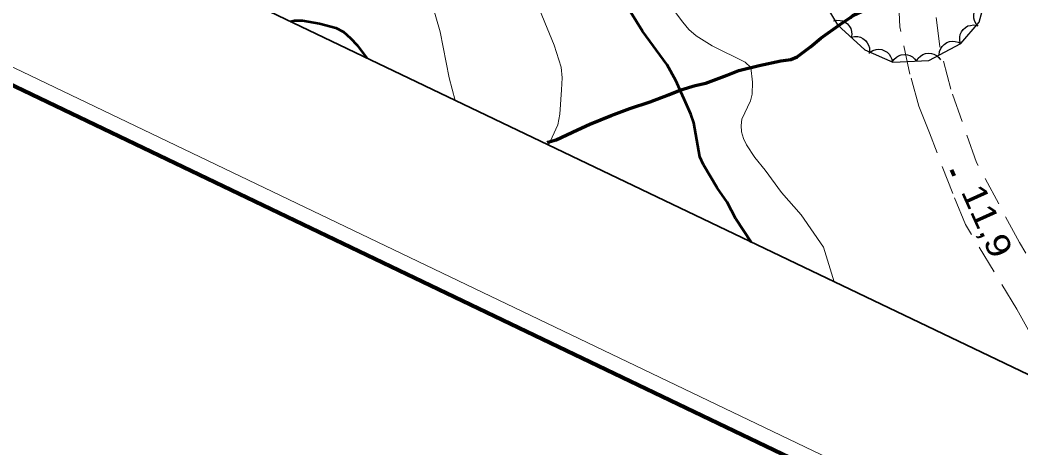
# Model space of a CAD drawing. Extents: x 355726 to 357533, y 5103782 to 5105258.
# Drawn here: x 355806.3 to 355868.2, y 5104403.8 to 5104430.3 of the extents above; entities that cross this region are included whole.
import ezdxf

# ---------------------------------------------------------------- set-up
doc = ezdxf.new("R2010")
doc.units = 0
doc.header["$LTSCALE"] = 0.6
for name, pattern in [('DOT_DASHED', [7.7, 5, -1.2, 0.3, -1.2]), ('LONG_DASHED', [7.5, 6, -1.5]), ('MEDIUM_DASHED', [4.5, 3, -1.5])]:
    doc.linetypes.add(name, pattern=pattern)
for name, color, linetype, lineweight in [('1', 7, 'LONG_DASHED', 53), ('19', 7, 'Continuous', 13), ('2', 7, 'LONG_DASHED', 13), ('22', 7, 'Continuous', 13), ('3', 7, 'Continuous', 140), ('44', 7, 'Continuous', 25), ('60', 7, 'Continuous', 13)]:
    doc.layers.add(name, color=color, linetype=linetype, lineweight=lineweight)

msp = doc.modelspace()

# ---------------------------------------------------------------- linework, layer by layer
at = {"layer": '1', "linetype": 'Continuous'}
msp.add_lwpolyline([(355851.59, 5104416.57), (355850.64, 5104418.01), (355850.1, 5104419.05), (355849.48, 5104419.93), (355848.64, 5104421.36), (355848.42, 5104421.84), (355848.04, 5104423.96), (355847.85, 5104424.48), (355846.92, 5104426.57), (355846.38, 5104427.55), (355844.86, 5104429.63), (355843.85, 5104431.26)], dxfattribs=at)
at = {"layer": '1'}
msp.add_lwpolyline([(355823.06, 5104430.23), (355823.3, 5104430.29), (355823.8, 5104430.3), (355824.85, 5104430.11), (355825.86, 5104429.84), (355826.34, 5104429.59), (355826.78, 5104429.2), (355827.19, 5104428.76), (355827.79, 5104427.96)], dxfattribs=at)
at = {"layer": '19', "linetype": 'MEDIUM_DASHED'}
for points in [[(355870.09, 5104408.75), (355868.05, 5104412.41), (355864.88, 5104417.65), (355864.08, 5104419.57), (355862.64, 5104423.33), (355861.99, 5104424.98), (355861.43, 5104426.97), (355860.8, 5104429.89), (355860.71, 5104431.93), (355860.63, 5104433.62), (355860.67, 5104435.27), (355860.96, 5104438.95), (355862.04, 5104446.11), (355862.5, 5104448.51), (355863.18, 5104450.59), (355863.73, 5104453.33), (355864.37, 5104455.53), (355864.99, 5104458.03), (355865.95, 5104460.45), (355867.14, 5104463.61), (355867.98, 5104465.8), (355869.15, 5104468.59)], [(355871.35, 5104411.24), (355868.21, 5104416.55), (355865.56, 5104421.49), (355863.97, 5104426.03), (355863.28, 5104428.68), (355862.92, 5104431.54), (355862.93, 5104434.2), (355863.07, 5104436.38), (355863.26, 5104438.83), (355863.47, 5104440.78), (355864, 5104442.94), (355865.27, 5104449.22), (355865.5, 5104450.86), (355865.8, 5104452.26), (355866.17, 5104453.63), (355866.58, 5104454.88), (355867.83, 5104459.2), (355868.43, 5104460.43)]]:
    msp.add_lwpolyline(points, dxfattribs=at)
at = {"layer": '2'}
for points in [[(355831.75, 5104431.61), (355832.32, 5104429.59), (355832.88, 5104426.74), (355833.25, 5104425.34)], [(355839.04, 5104422.58), (355839.62, 5104423.82), (355839.75, 5104424.5), (355839.85, 5104425.99), (355839.88, 5104426.73), (355839.82, 5104427.41), (355839.39, 5104428.76), (355838.19, 5104431.7)]]:
    msp.add_lwpolyline(points, dxfattribs=at)
at = {"layer": '2', "linetype": 'Continuous'}
msp.add_lwpolyline([(355856.74, 5104414.11), (355856.07, 5104416.25), (355854.69, 5104418.26), (355853.47, 5104419.63), (355852.46, 5104421.03), (355851.82, 5104421.8), (355851.3, 5104422.59), (355851.11, 5104422.99), (355850.99, 5104423.4), (355850.97, 5104423.79), (355851.02, 5104424.18), (355851.56, 5104425.32), (355851.65, 5104425.72), (355851.68, 5104426.48), (355851.58, 5104427.38), (355851.22, 5104427.7), (355849.17, 5104428.73), (355848.18, 5104429.34), (355847.74, 5104429.74), (355847.36, 5104430.18), (355846.6, 5104431.2)], dxfattribs=at)
at = {"layer": '22', "linetype": 'LONG_DASHED', "lineweight": 70}
msp.add_lwpolyline([(355838.96, 5104422.73), (355839, 5104422.75), (355839.51, 5104422.91), (355840.83, 5104423.51), (355841.6, 5104423.88), (355842.93, 5104424.41), (355844.07, 5104424.84), (355845.34, 5104425.26), (355846.48, 5104425.68), (355847.24, 5104425.99), (355848.13, 5104426.26), (355848.78, 5104426.41), (355850.11, 5104426.9), (355850.82, 5104427.2), (355852.09, 5104427.51), (355853.44, 5104427.79), (355854.06, 5104427.88), (355854.45, 5104428.04), (355855.26, 5104428.66), (355855.91, 5104429.2), (355857.13, 5104430.07), (355857.75, 5104430.48), (355857.89, 5104430.59), (355860.71, 5104431.93)], dxfattribs=at)
at = {"layer": '3'}
msp.add_line((355864.01, 5104421.04), (355864.17, 5104420.67), dxfattribs=at)
at = {"layer": '44', "linetype": 'DOT_DASHED'}
msp.add_lwpolyline([(355869.03, 5104478.9), (355864.17, 5104473.77), (355861.32, 5104470.45), (355858.63, 5104465.67), (355856.61, 5104460.32), (355854.91, 5104455.18), (355853.82, 5104450.09), (355853.27, 5104446.66), (355853.06, 5104443.83), (355852.88, 5104440), (355853, 5104437.76), (355853.94, 5104434.87), (355856.95, 5104430.03), (355858.64, 5104428.48), (355860.37, 5104427.7), (355862.61, 5104427.82), (355864.58, 5104428.87), (355865.72, 5104430.19), (355866.1, 5104431.56), (355866.58, 5104435.22), (355867.9, 5104437.23), (355870.74, 5104440.15)], dxfattribs=at)
at = {"layer": '44'}
for points in [[(355865.65, 5104429.94), (355865.52, 5104430.1), (355865.43, 5104430.29), (355865.39, 5104430.44), (355865.39, 5104430.62), (355865.42, 5104430.8), (355865.51, 5104430.98), (355865.59, 5104431.12), (355865.72, 5104431.23), (355865.88, 5104431.33), (355866.05, 5104431.39)], [(355856.69, 5104430.27), (355856.9, 5104430.31), (355857.1, 5104430.3), (355857.26, 5104430.27), (355857.42, 5104430.19), (355857.56, 5104430.08), (355857.68, 5104429.92), (355857.77, 5104429.79), (355857.81, 5104429.61), (355857.83, 5104429.43), (355857.8, 5104429.25)], [(355864.57, 5104428.86), (355864.52, 5104429.06), (355864.52, 5104429.26), (355864.55, 5104429.43), (355864.63, 5104429.58), (355864.73, 5104429.73), (355864.88, 5104429.86), (355865.02, 5104429.95), (355865.19, 5104429.99), (355865.37, 5104430.02), (355865.55, 5104429.99)], [(355857.8, 5104429.25), (355858, 5104429.3), (355858.2, 5104429.29), (355858.37, 5104429.26), (355858.52, 5104429.17), (355858.67, 5104429.06), (355858.79, 5104428.91), (355858.87, 5104428.77), (355858.92, 5104428.6), (355858.93, 5104428.42), (355858.9, 5104428.24)], [(355863.24, 5104428.16), (355863.27, 5104428.37), (355863.34, 5104428.55), (355863.43, 5104428.69), (355863.56, 5104428.81), (355863.71, 5104428.92), (355863.89, 5104428.98), (355864.05, 5104429.01), (355864.23, 5104428.99), (355864.41, 5104428.95), (355864.57, 5104428.86)], [(355858.97, 5104428.33), (355859.14, 5104428.44), (355859.34, 5104428.49), (355859.51, 5104428.51), (355859.68, 5104428.49), (355859.85, 5104428.42), (355860.01, 5104428.32), (355860.14, 5104428.21), (355860.23, 5104428.06), (355860.3, 5104427.89), (355860.33, 5104427.72)], [(355860.33, 5104427.7), (355860.44, 5104427.88), (355860.59, 5104428.01), (355860.73, 5104428.11), (355860.89, 5104428.16), (355861.08, 5104428.19), (355861.27, 5104428.16), (355861.43, 5104428.13), (355861.58, 5104428.04), (355861.72, 5104427.92), (355861.83, 5104427.78)], [(355861.83, 5104427.78), (355861.94, 5104427.96), (355862.09, 5104428.09), (355862.22, 5104428.19), (355862.39, 5104428.24), (355862.57, 5104428.27), (355862.76, 5104428.24), (355862.92, 5104428.21), (355863.08, 5104428.12), (355863.22, 5104428), (355863.33, 5104427.86)]]:
    msp.add_lwpolyline(points, dxfattribs=at)
at = {"layer": '60', "lineweight": 158}
msp.add_lwpolyline([(355725.74, 5104464.62), (357152.72, 5103781.6), (357532.66, 5104575.38), (356105.68, 5105258.4)], close=True, dxfattribs=at)
at = {"layer": '60'}
msp.add_lwpolyline([(355727.1, 5104465.08), (357152.24, 5103782.93), (357531.32, 5104574.91), (356106.18, 5105257.06)], close=True, dxfattribs=at)
at = {"layer": '60', "lineweight": 35}
msp.add_lwpolyline([(355740.43, 5104469.78), (356913.03, 5103908.53), (357283.46, 5104682.46), (356110.86, 5105243.71)], close=True, dxfattribs=at)

# ---------------------------------------------------------------- texts
at = {"layer": '3', "width": 1.2}
msp.add_text('11,9   ', height=1.5, rotation=294.262, dxfattribs=at).set_placement((355864.57, 5104419.7))

doc.saveas('drawing.dxf')
